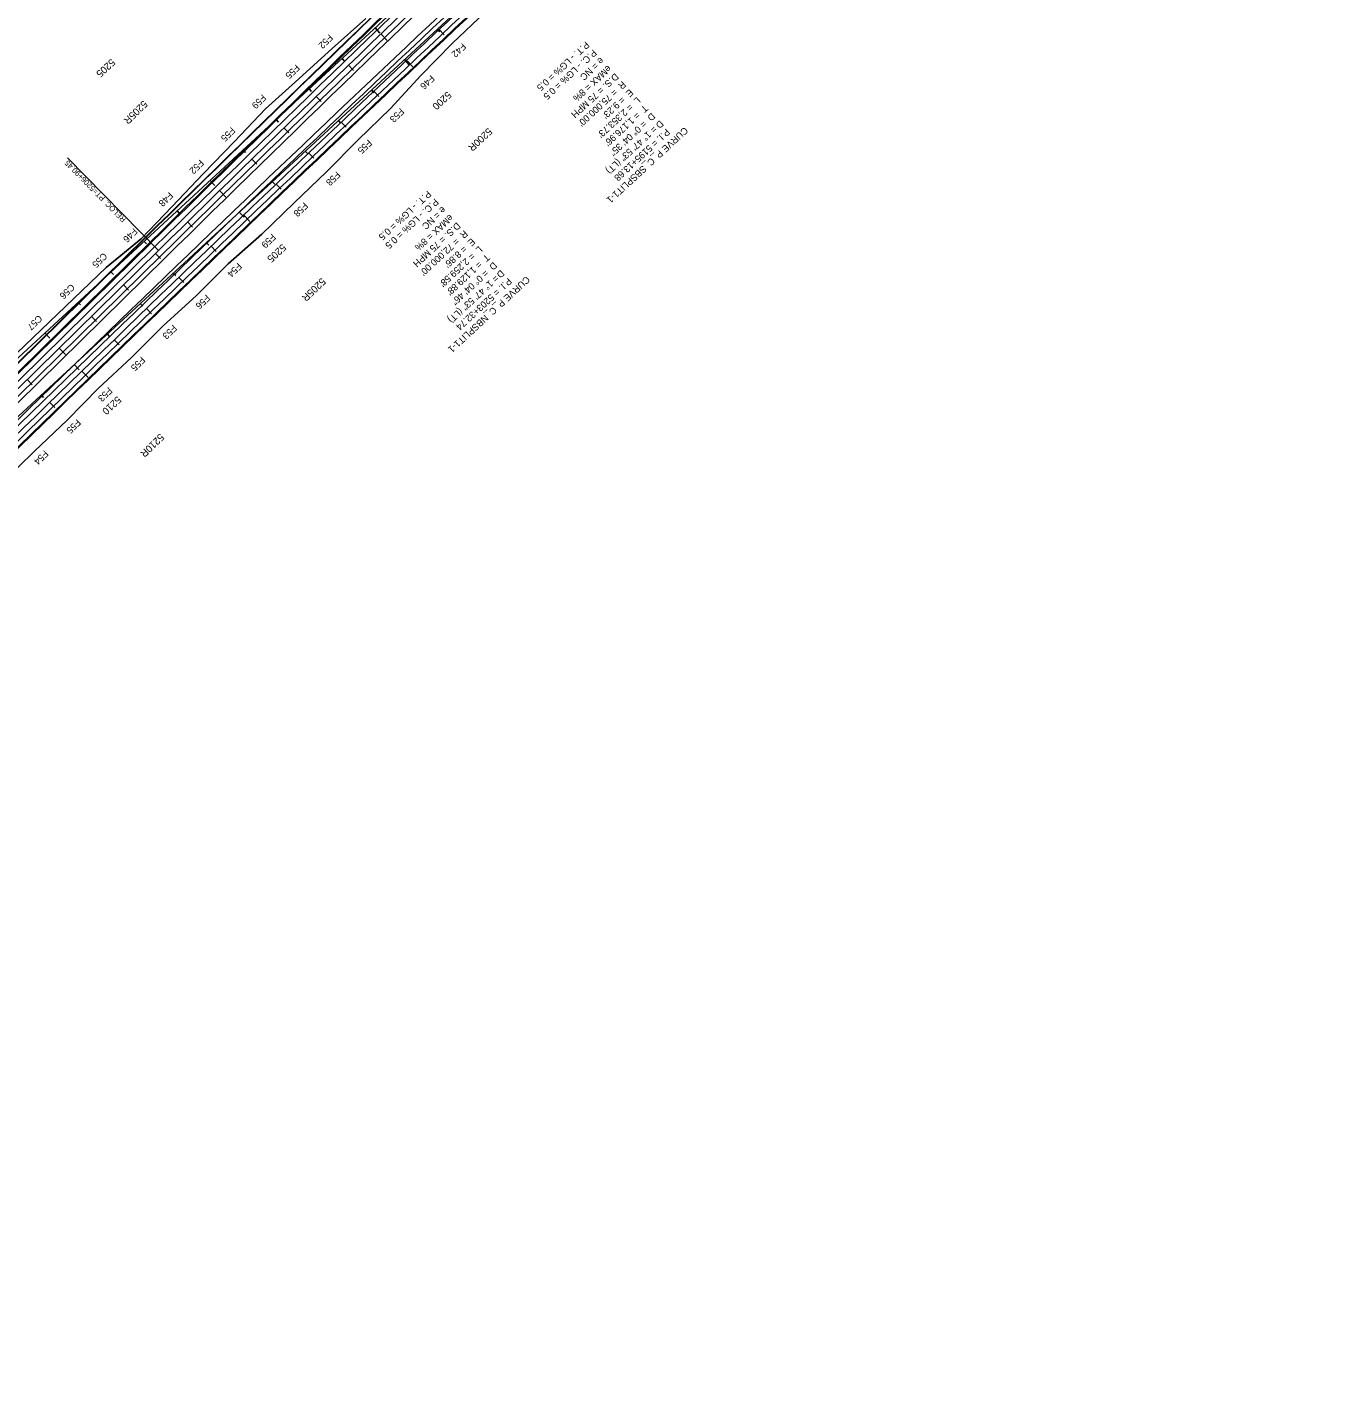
# Model space of a CAD drawing. Extents: x 2160877 to 2175861, y 601747 to 617724.
# Drawn here: x 2169344 to 2172272, y 608836 to 611848 of the extents above; entities that cross this region are included whole.
import ezdxf

# ---------------------------------------------------------------- set-up
doc = ezdxf.new("R2010")
doc.units = 0
for name, color, linetype in [('RD_HC_Cl', 7, 'Continuous'), ('RD_HC_CL_Rel', 7, 'Continuous'), ('RD_HC_Data_Rel', 7, 'Continuous'), ('RD_HC_Data_Tic', 7, 'Continuous'), ('RD_HC_Data_Tic_Rel', 7, 'Continuous'), ('RD_HC_TX_Rel_Sta50', 7, 'Continuous'), ('RD_HC_TX_StaOther', 7, 'Continuous'), ('RD_PD_CstnLmt', 7, 'Continuous'), ('RD_PD_CstnLmt_TX', 7, 'Continuous'), ('RD_PD_Final_LnLine', 7, 'Continuous'), ('RD_PD_Final_TrvlWay', 7, 'Continuous'), ('RD_PD_GR', 7, 'Continuous'), ('RD_PD_MedBWall', 7, 'Continuous')]:
    doc.layers.add(name, color=color, linetype=linetype)

msp = doc.modelspace()

# ---------------------------------------------------------------- linework, layer by layer
at = {"layer": 'RD_HC_Cl'}
for p, q in [((2172207.3, 613775.1), (2163672.2, 605893.8)), ((2172272.5, 613704.6), (2163737.4, 605823.3))]:
    msp.add_line(p, q, dxfattribs=at)
at = {"layer": 'RD_HC_CL_Rel'}
msp.add_line((2169636.8, 611351.3), (2168950.1, 610676), dxfattribs=at)
for centre, radius in [((2222221.5, 557873.6), 75000), ((2219616.9, 559421.3), 72000)]:
    msp.add_arc(centre, radius, 132.719474, 134.517591, dxfattribs=at)
at = {"layer": 'RD_HC_Data_Rel'}
msp.add_line((2169636.8, 611351.3), (2169434.4, 611557.2), dxfattribs=at)
at = {"layer": 'RD_HC_Data_Tic'}
for p, q in [((2170118.8, 611846.6), (2170129.6, 611834.8)), ((2170257.4, 611843.9), (2170262.8, 611838)), ((2170045.3, 611778.7), (2170050.7, 611772.8)), ((2170183.9, 611776), (2170194.7, 611764.3)), ((2169971.8, 611710.9), (2169977.3, 611705)), ((2170110.4, 611708.2), (2170115.9, 611702.3)), ((2169898.4, 611643), (2169903.8, 611637.2)), ((2170037, 611640.3), (2170042.4, 611634.5)), ((2169824.9, 611575.2), (2169830.3, 611569.3)), ((2169963.5, 611572.5), (2169968.9, 611566.6)), ((2169751.4, 611507.4), (2169762.3, 611495.6)), ((2169890, 611504.7), (2169895.4, 611498.8)), ((2169678, 611439.5), (2169683.4, 611433.6)), ((2169816.5, 611436.8), (2169827.4, 611425.1)), ((2169604.5, 611371.7), (2169609.9, 611365.8)), ((2169743.1, 611369), (2169748.5, 611363.1)), ((2169531, 611303.8), (2169536.4, 611298)), ((2169669.6, 611301.1), (2169675, 611295.3)), ((2169457.5, 611236), (2169463, 611230.1)), ((2169596.1, 611233.3), (2169601.6, 611227.4)), ((2169384.1, 611168.1), (2169394.9, 611156.4)), ((2169522.7, 611165.5), (2169528.1, 611159.6)), ((2169449.2, 611097.6), (2169460.1, 611085.9)), ((2169375.7, 611029.8), (2169381.2, 611023.9))]:
    msp.add_line(p, q, dxfattribs=at)
at = {"layer": 'RD_HC_Data_Tic_Rel'}
for p, q in [((2170131.4, 611833.1), (2170145.3, 611818.7)), ((2170261.6, 611843.2), (2170272.5, 611831.5)), ((2170059.5, 611763.6), (2170070.6, 611752.1)), ((2170188.8, 611774.6), (2170202.5, 611760)), ((2170116.1, 611705.9), (2170127.1, 611694.2)), ((2169987.7, 611694), (2169998.8, 611682.5)), ((2169916, 611624.3), (2169927.1, 611612.8)), ((2170043.6, 611637.1), (2170054.6, 611625.5)), ((2169844.3, 611554.5), (2169855.5, 611543.1)), ((2169971.1, 611568.2), (2169982.1, 611556.6)), ((2169898.7, 611499.2), (2169909.8, 611487.6)), ((2169772.8, 611484.6), (2169786.8, 611470.3)), ((2169701.4, 611414.7), (2169712.6, 611403.2)), ((2169826.4, 611430.1), (2169840.3, 611415.6)), ((2169630, 611344.6), (2169641.2, 611333.2)), ((2169754.3, 611360.8), (2169765.3, 611349.3)), ((2169682.2, 611291.5), (2169693.3, 611280)), ((2169558.7, 611274.5), (2169569.9, 611263.1)), ((2169610.2, 611222.1), (2169621.3, 611210.6)), ((2169487.4, 611204.4), (2169498.6, 611193)), ((2169416.1, 611134.2), (2169430.1, 611120)), ((2169538.3, 611152.6), (2169549.4, 611141.1)), ((2169466.5, 611083), (2169480.4, 611068.7)), ((2169344.8, 611064.1), (2169356, 611052.7)), ((2169394.8, 611013.3), (2169405.9, 611001.9))]:
    msp.add_line(p, q, dxfattribs=at)
at = {"layer": 'RD_PD_CstnLmt'}
for p, q in [((2170097.9, 611867.7), (2170023.5, 611800.8)), ((2170363.2, 611881), (2170290.7, 611812.3)), ((2170023.5, 611800.8), (2169949.4, 611733.5)), ((2170290.7, 611812.3), (2170220.6, 611740.9)), ((2169949.4, 611733.5), (2169874.7, 611666.7)), ((2170220.6, 611740.9), (2170152.7, 611667.2)), ((2169874.7, 611666.7), (2169805.9, 611593.9)), ((2170152.7, 611667.2), (2170081.3, 611597.4)), ((2169805.9, 611593.9), (2169736.4, 611521.8)), ((2170081.3, 611597.4), (2170010.8, 611526.5)), ((2169736.4, 611521.8), (2169667.5, 611449.2)), ((2170010.8, 611526.5), (2169938.5, 611457.5)), ((2169667.5, 611449.2), (2169598, 611377.1)), ((2169938.5, 611457.5), (2169867, 611387.6)), ((2169598, 611377.1), (2169520.2, 611313.6)), ((2169867, 611387.6), (2169791.6, 611321.9)), ((2169520.2, 611313.6), (2169448.1, 611244.4)), ((2169791.6, 611321.9), (2169721, 611251.2)), ((2169721, 611251.2), (2169647, 611184)), ((2169448.1, 611244.4), (2169375.9, 611175.1)), ((2169375.9, 611175.1), (2169303.7, 611105.9)), ((2169647, 611184), (2169576.5, 611113.2)), ((2169576.5, 611113.2), (2169503.4, 611045)), ((2169503.4, 611045), (2169433.2, 610973.9)), ((2169433.2, 610973.9), (2169361.1, 610904.6)), ((2169361.1, 610904.6), (2169289.3, 610835.1))]:
    msp.add_line(p, q, dxfattribs=at)
at = {"layer": 'RD_PD_Final_LnLine'}
for p, q in [((2168941.7, 610684.6), (2169628.4, 611359.8)), ((2168958.5, 610667.5), (2169645.3, 611342.7))]:
    msp.add_line(p, q, dxfattribs=at)
for centre, radius in [((2222221.5, 557873.6), 75012), ((2222221.5, 557873.6), 74988), ((2219616.9, 559421.3), 72012), ((2219616.9, 559421.3), 71988)]:
    msp.add_arc(centre, radius, 132.719474, 134.517591, dxfattribs=at)
at = {"layer": 'RD_PD_Final_TrvlWay'}
for p, q in [((2168931.7, 610694.8), (2169618.4, 611370.1)), ((2168933.3, 610693.2), (2169620.1, 611368.4)), ((2168965.5, 610660.3), (2169652.3, 611335.6))]:
    msp.add_line(p, q, dxfattribs=at)
for centre, radius in [((2222220.1, 557875.1), 75024.3), ((2222220.1, 557875.1), 75022), ((2222221.5, 557873.6), 74978), ((2219616.9, 559421.3), 72022), ((2219616.9, 559421.3), 71978)]:
    msp.add_arc(centre, radius, 132.719474, 134.517591, dxfattribs=at)
at = {"layer": 'RD_PD_GR'}
msp.add_arc((2219616.9, 559421.3), 71976, 132.719474, 134.517591, dxfattribs=at)
at = {"layer": 'RD_PD_MedBWall'}
for p, q in [((2168921.2, 610705.5), (2169607.9, 611380.8)), ((2168921.9, 610704.8), (2169608.6, 611380.1))]:
    msp.add_line(p, q, dxfattribs=at)
for radius in [75039.3, 75038.3]:
    msp.add_arc((2222220.1, 557875.1), radius, 132.719474, 134.517591, dxfattribs=at)

# ---------------------------------------------------------------- texts
at = {"layer": 'RD_HC_Data_Rel'}
for s, height, rotation, p in [('P.T. - LG% = 0.5', 15, 222.7195, (2170587.3, 611817.4)), ('P.C. - LG% = 0.5', 15, 222.7195, (2170603.6, 611799.8)), ('eMAX = 8%', 15, 222.7195, (2170636.1, 611764.5)), ('e = NC', 15, 222.7195, (2170619.8, 611782.1)), ('D.S. = 75 MPH', 15, 222.7195, (2170652.4, 611746.9)), ("R  = 75,000.00'", 15, 222.7195, (2170668.7, 611729.2)), ("E  = 9.23'", 15, 222.7195, (2170685, 611711.6)), ("L  = 2,353.73'", 15, 222.7195, (2170701.2, 611694)), ("T  = 1,176.96'", 15, 222.7195, (2170717.5, 611676.3)), ('D  = 0%%d 04\' 35"', 15, 222.7195, (2170733.8, 611658.7)), ('   = 1%%d 47\' 53" (LT)', 15, 222.7195, (2170750.1, 611641.1)), ('CURVE P_C_SBSPLIT1-1', 15, 222.7195, (2170806.9, 611627.1)), ('P.I. = 5195+13.68', 15, 222.7195, (2170766.4, 611623.4)), ('D ', 15, 222.7195, (2170752.4, 611642.1)), ('RELOC. PT=5206+90.45', 12, 134.5176, (2169565.3, 611421.2)), ('P.T. - LG% = 0.5', 15, 222.7195, (2170235.4, 611485.5)), ('P.C. - LG% = 0.5', 15, 222.7195, (2170251.7, 611467.9)), ('e = NC', 15, 222.7195, (2170268, 611450.2)), ('D.S. = 75 MPH', 15, 222.7195, (2170300.5, 611415)), ('eMAX = 8%', 15, 222.7195, (2170284.2, 611432.6)), ("R  = 72,000.00'", 15, 222.7195, (2170316.8, 611397.3)), ("E  = 8.86'", 15, 222.7195, (2170333.1, 611379.7)), ("L  = 2,259.58'", 15, 222.7195, (2170349.4, 611362.1)), ("T  = 1,129.88'", 15, 222.7195, (2170365.7, 611344.4)), ('D  = 0%%d 04\' 46"', 15, 222.7195, (2170381.9, 611326.8)), ('   = 1%%d 47\' 53" (LT)', 15, 222.7195, (2170398.2, 611309.2)), ('CURVE P_C_NBSPLIT1-1', 15, 222.7195, (2170455, 611295.2)), ('P.I. = 5203+32.74', 15, 222.7195, (2170414.5, 611291.5)), ('D ', 15, 222.7195, (2170398.2, 611309.2))]:
    msp.add_text(s, height=height, rotation=rotation, dxfattribs=at).set_placement(p)
at = {"layer": 'RD_HC_TX_Rel_Sta50'}
for s, rotation, p in [('5205R', 224.3721, (2169603, 611686.3)), ('5200R', 223.3538, (2170370.3, 611625.4)), ('5205R', 223.7517, (2169999.8, 611291.5)), ('5210R', 224.1496, (2169640, 610944.9))]:
    msp.add_text(s, height=16, rotation=rotation, dxfattribs=at).set_placement(p)
at = {"layer": 'RD_HC_TX_StaOther'}
for s, p in [('5205', (2169531.6, 611779.1)), ('5200', (2170279.7, 611706.6)), ('5205', (2169912, 611367.1)), ('5210', (2169545, 611028.2))]:
    msp.add_text(s, height=16, rotation=222.7195, dxfattribs=at).set_placement(p)
at = {"layer": 'RD_PD_CstnLmt_TX'}
for s, rotation, p in [('F52', 224.0665, (2170016.3, 611833.6)), ('F42', 223.2742, (2170312.7, 611813.9)), ('F55', 224.1429, (2169942.4, 611766.5)), ('F46', 223.3538, (2170242.8, 611742.7)), ('F59', 224.2193, (2169867.7, 611699.8)), ('F53', 223.4334, (2170175, 611669.2)), ('F55', 224.2957, (2169798.9, 611626.9)), ('F55', 223.513, (2170103.5, 611599.3)), ('F52', 224.3721, (2169729.1, 611554.7)), ('F58', 223.5926, (2170033.1, 611528.4)), ('F48', 224.4485, (2169660.4, 611482.3)), ('F58', 223.6721, (2169960.8, 611459.5)), ('F46', 224.5176, (2169581.3, 611402.4)), ('F59', 223.7517, (2169889.3, 611389.7)), ('C55', 224.5176, (2169513.9, 611347.5)), ('F54', 223.8313, (2169813.6, 611324.8)), ('C56', 224.5176, (2169441.7, 611278.2)), ('F56', 223.9109, (2169743, 611254.2)), ('C57', 224.5176, (2169369.5, 611208.9)), ('F53', 223.9904, (2169669.1, 611187.1)), ('F55', 224.07, (2169598.6, 611116.3)), ('F53', 224.1496, (2169525.5, 611048.1)), ('F55', 224.2292, (2169455.2, 610977.1)), ('F54', 224.3087, (2169383, 610907.7))]:
    msp.add_text(s, height=15, rotation=rotation, dxfattribs=at).set_placement(p)

doc.saveas('drawing.dxf')
